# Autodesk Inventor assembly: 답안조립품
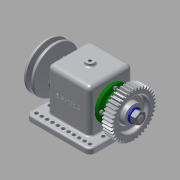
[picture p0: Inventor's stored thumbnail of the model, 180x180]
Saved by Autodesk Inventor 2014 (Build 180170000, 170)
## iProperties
Created: 2018-11
Part Number: 답안조립품
Document SubType Name: Assembly
Designer: kh
Author: kh
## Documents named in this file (13)
- C:\Users\kh\Desktop\481107V1029\답안조립품.iam
- C:\Users\kh\Desktop\481107V1029\본체.ipt
- C:\Users\kh\Desktop\481107V1029\V벨트풀리.ipt
- C:\Users\kh\Desktop\481107V1029\너트 M12x1.25.ipt
- C:\Users\kh\Desktop\481107V1029\베어링 6203.ipt
- C:\Users\kh\Desktop\481107V1029\볼트 M4.ipt
- C:\Users\kh\Desktop\481107V1029\부시.ipt
- C:\Users\kh\Desktop\481107V1029\스퍼기어.ipt
- C:\Users\kh\Desktop\481107V1029\오일 실 26 38 8.ipt
- C:\Users\kh\Desktop\481107V1029\와셔 12x24.ipt
- C:\Users\kh\Desktop\481107V1029\축.ipt
- C:\Users\kh\Desktop\481107V1029\커버.ipt
- C:\Users\kh\Desktop\481107V1029\키 5x5x12.ipt
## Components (1 placed, 1 different names)
1. V벨트풀리:1
